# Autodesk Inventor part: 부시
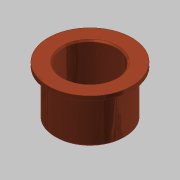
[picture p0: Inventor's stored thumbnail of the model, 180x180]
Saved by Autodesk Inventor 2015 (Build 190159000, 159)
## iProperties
Created: 2015-10
Part Number: 부시
Document SubType Name: Modeling
Designer: mdu
Density: 7.86 g/cm^3
Material: 강철, 연강
Mass: 246.97 g
Surface Area: 129.264 cm^2
Volume: 31.4212 cm^3
Appearance: Copper - Satin
Author: mdu
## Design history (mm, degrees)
sketch "스케치1"
  geometry: C1 r 31 at (0, 0) reference; C2 r 25 at (0, 0) reference; C3 r 30 at (0, 0) reference; 1 further point
  node "참조1"
  node "참조2"
  node "참조4"
extrude "돌출1" new body sketch "스케치1" distance "d0" = 3; taper "d1" = 0 deg
extrude "돌출2" join sketch "스케치1" distance "d2" = 35; taper "d3" = 0 deg
chamfer "모따기1" distance "d6" = 1; stored, may be unused: second distance "d7" = 2, angle "d8" = 45 deg
sketch "스케치3"
  geometry: C1 r 19 at (0, 0); 1 further point
  constraints: 1 centre point, 1 coincident
  dimensions: "d13" = 38 diameter of C1
extrude "돌출4" cut sketch "스케치3" stored distance "d14" = 10; taper "d15" = 0 deg
chamfer "모따기3" distance "d16" = 1; stored, may be unused: second distance "d17" = 2, angle "d18" = 45 deg
node "솔리드1"
